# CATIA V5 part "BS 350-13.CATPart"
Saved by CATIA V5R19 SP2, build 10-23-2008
Part number: BS 300-13
Bounding box of the stored display mesh (mm): x -15.868 to 15.868, y -15.868 to 15.868, z 0 to 56
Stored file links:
  C:\Users\Bora\Desktop\3D Katı model\BS serisi\BS 300\BS 300-13.CATPart
  C:\Program Files\Dassault Systemes\B19\intel_a\reffiles\standard\MetricThickPitch.txt
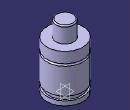
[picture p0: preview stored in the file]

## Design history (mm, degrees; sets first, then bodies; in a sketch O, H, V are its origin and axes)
Body1 (main body)
  Sketch1 on yz-plane, origin (0, 0, 0), H (0, 1, 0), V (0, 0, 1)
    point P1 (8, 55)
    point P3 (8, 55)
    point P5 (16, 32.5)
    point P6 (16, 30.5)
    point P9 (16, 32.5)
    point P14 (16, 30.5)
    line L1 (8, 55) -> (8, 42)
    arc A1 centre (7, 55) radius 1 from (8, 55) to (7, 56) ccw
    arc A2 centre (16, 31.5) radius 1 from (16, 32.5) to (16, 30.5) ccw
    line L2 (16, 0) -> (16, 4)
    line L3 (16, 32.5) -> (16, 42)
    line L4 (14.5, 7.5) -> (14.5, 4)
    line L5 (16, 7.5) -> (16, 30.5)
    line L6 (7, 56) -> (0, 56)
    point P15 (0, 56)
    line L7 (8, 42) -> (16, 42)
    line L8 (0, 0) -> (16, 0)
    line L9 (14.5, 4) -> (16, 4)
    line L10 (14.5, 7.5) -> (16, 7.5)
    coincidence: P15 V, P1 P3, P5 P9, P6 P14
    tangency: L6 A1
    horizontal: L7 H, L8 H, L9 H, L10 H
  Shaft1: profile Sketch1, axis Sketch1.V, angle 360
  Sketch2 on face of Shaft1 from Sketch1.L8, origin (0, 0, 0), H (1, 0, 0), V (0, -1, 0)
    point P1 (0, 0)
  Hole1: placed by Sketch2, at (0, 0, 0) direction (0, 0, 1), diameter 6.647, depth 4, threaded "M8", thread diameter 8, thread depth 4, pitch 1.25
